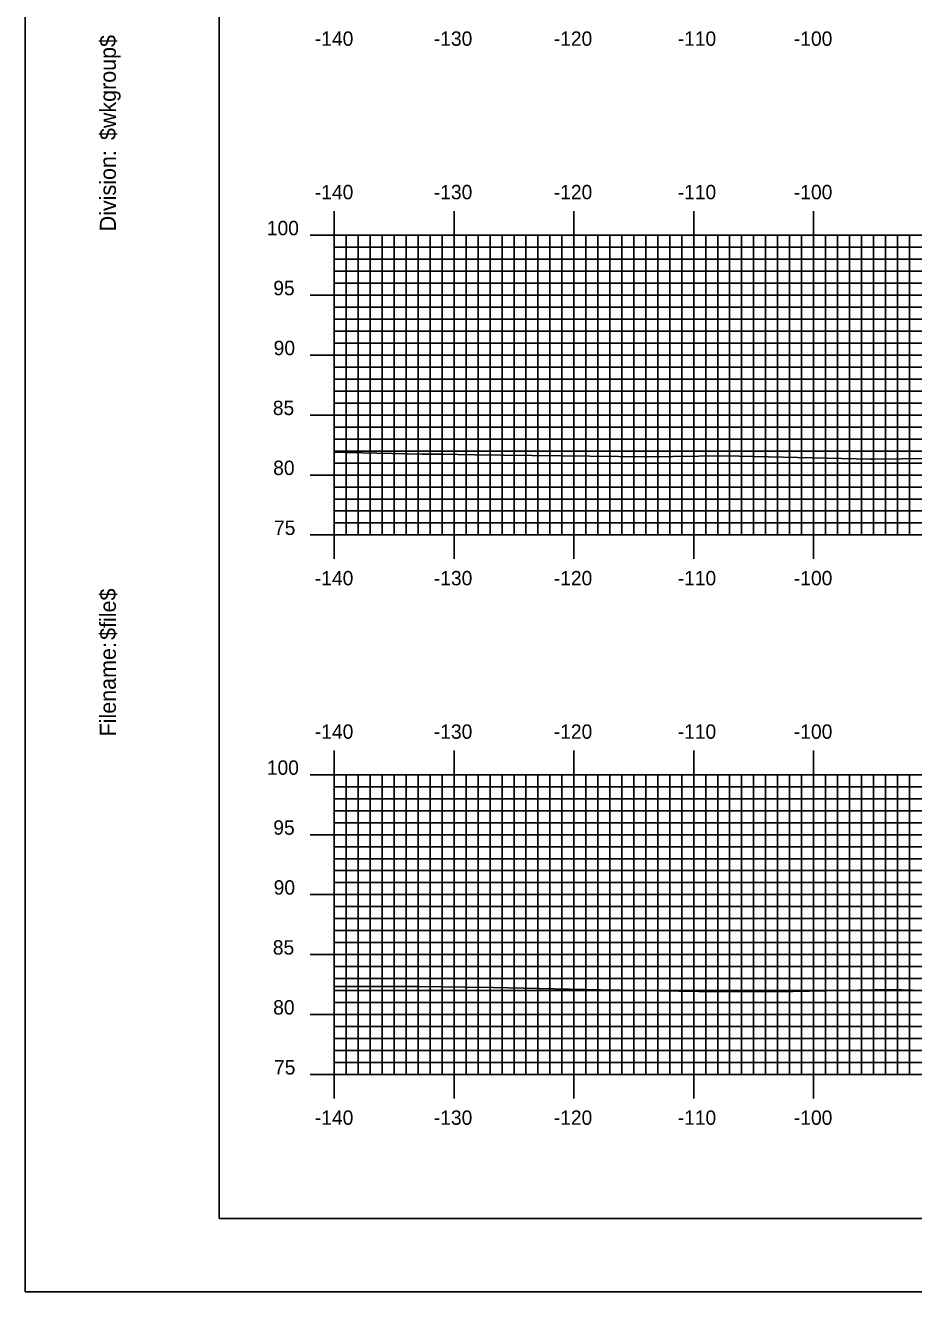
# Model space of a CAD drawing. Extents: x 856323 to 856666, y 364765 to 364985.
# Drawn here: x 856323 to 856397.1, y 364765.2 to 364870.8 of the extents above; entities that cross this region are included whole.
import ezdxf

# ---------------------------------------------------------------- set-up
doc = ezdxf.new("R2010")
doc.units = 0
for name, color, linetype in [('BORDER', 7, 'Continuous'), ('H_V ANNOTATION', 7, 'Continuous'), ('MAJOR', 7, 'Continuous'), ('MINOR', 7, 'Continuous'), ('PLOT BOUNDARY', 7, 'Continuous'), ('S_Roadway_Centerline', 7, 'Continuous')]:
    doc.layers.add(name, color=color, linetype=linetype)

msp = doc.modelspace()

# ---------------------------------------------------------------- linework, layer by layer
at = {"layer": 'BORDER'}
msp.add_lwpolyline([(856339.17, 364771.3), (856659.17, 364771.3), (856659.17, 364981.3), (856339.17, 364981.3)], close=True, dxfattribs=at)
at = {"layer": 'MAJOR'}
for p, q in [((856348.77, 364855.31), (856348.77, 364853.3)), ((856358.77, 364855.31), (856358.77, 364853.3)), ((856368.77, 364855.31), (856368.77, 364853.3)), ((856378.77, 364855.31), (856378.77, 364853.3)), ((856388.77, 364855.31), (856388.77, 364853.3)), ((856346.76, 364853.3), (856348.77, 364853.3)), ((856348.77, 364853.3), (856628.77, 364853.3)), ((856348.77, 364828.3), (856348.77, 364853.3)), ((856348.77, 364828.3), (856348.77, 364853.3)), ((856348.77, 364853.3), (856628.77, 364853.3)), ((856358.77, 364828.3), (856358.77, 364853.3)), ((856368.77, 364828.3), (856368.77, 364853.3)), ((856378.77, 364828.3), (856378.77, 364853.3)), ((856388.77, 364828.3), (856388.77, 364853.3)), ((856346.76, 364848.3), (856348.77, 364848.3)), ((856348.77, 364848.3), (856628.77, 364848.3)), ((856346.76, 364843.3), (856348.77, 364843.3)), ((856348.77, 364843.3), (856628.77, 364843.3)), ((856346.76, 364838.3), (856348.77, 364838.3)), ((856348.77, 364838.3), (856628.77, 364838.3)), ((856346.76, 364833.3), (856348.77, 364833.3)), ((856348.77, 364833.3), (856628.77, 364833.3)), ((856346.76, 364828.3), (856348.77, 364828.3)), ((856348.77, 364828.3), (856628.77, 364828.3)), ((856348.77, 364828.3), (856628.77, 364828.3)), ((856348.77, 364826.3), (856348.77, 364828.3)), ((856358.77, 364826.3), (856358.77, 364828.3)), ((856368.77, 364826.3), (856368.77, 364828.3)), ((856378.77, 364826.3), (856378.77, 364828.3)), ((856388.77, 364826.3), (856388.77, 364828.3)), ((856348.77, 364810.31), (856348.77, 364808.3)), ((856358.77, 364810.31), (856358.77, 364808.3)), ((856368.77, 364810.31), (856368.77, 364808.3)), ((856378.77, 364810.31), (856378.77, 364808.3)), ((856388.77, 364810.31), (856388.77, 364808.3)), ((856346.76, 364808.3), (856348.77, 364808.3)), ((856348.77, 364808.3), (856628.77, 364808.3)), ((856348.77, 364783.3), (856348.77, 364808.3)), ((856348.77, 364783.3), (856348.77, 364808.3)), ((856348.77, 364808.3), (856628.77, 364808.3)), ((856358.77, 364783.3), (856358.77, 364808.3)), ((856368.77, 364783.3), (856368.77, 364808.3)), ((856378.77, 364783.3), (856378.77, 364808.3)), ((856388.77, 364783.3), (856388.77, 364808.3)), ((856346.76, 364803.3), (856348.77, 364803.3)), ((856348.77, 364803.3), (856628.77, 364803.3)), ((856346.76, 364798.3), (856348.77, 364798.3)), ((856348.77, 364798.3), (856628.77, 364798.3)), ((856346.76, 364793.3), (856348.77, 364793.3)), ((856348.77, 364793.3), (856628.77, 364793.3)), ((856346.76, 364788.3), (856348.77, 364788.3)), ((856348.77, 364788.3), (856628.77, 364788.3)), ((856346.76, 364783.3), (856348.77, 364783.3)), ((856348.77, 364783.3), (856628.77, 364783.3)), ((856348.77, 364783.3), (856628.77, 364783.3)), ((856348.77, 364781.3), (856348.77, 364783.3)), ((856358.77, 364781.3), (856358.77, 364783.3)), ((856368.77, 364781.3), (856368.77, 364783.3)), ((856378.77, 364781.3), (856378.77, 364783.3)), ((856388.77, 364781.3), (856388.77, 364783.3))]:
    msp.add_line(p, q, dxfattribs=at)
at = {"layer": 'MINOR'}
for p, q in [((856349.77, 364828.3), (856349.77, 364853.3)), ((856350.77, 364828.3), (856350.77, 364853.3)), ((856351.77, 364828.3), (856351.77, 364853.3)), ((856352.77, 364828.3), (856352.77, 364853.3)), ((856353.77, 364828.3), (856353.77, 364853.3)), ((856354.77, 364828.3), (856354.77, 364853.3)), ((856355.77, 364828.3), (856355.77, 364853.3)), ((856356.77, 364828.3), (856356.77, 364853.3)), ((856357.77, 364828.3), (856357.77, 364853.3)), ((856359.77, 364828.3), (856359.77, 364853.3)), ((856360.77, 364828.3), (856360.77, 364853.3)), ((856361.77, 364828.3), (856361.77, 364853.3)), ((856362.77, 364828.3), (856362.77, 364853.3)), ((856363.77, 364828.3), (856363.77, 364853.3)), ((856364.77, 364828.3), (856364.77, 364853.3)), ((856365.77, 364828.3), (856365.77, 364853.3)), ((856366.77, 364828.3), (856366.77, 364853.3)), ((856367.77, 364828.3), (856367.77, 364853.3)), ((856369.77, 364828.3), (856369.77, 364853.3)), ((856370.77, 364828.3), (856370.77, 364853.3)), ((856371.77, 364828.3), (856371.77, 364853.3)), ((856372.77, 364828.3), (856372.77, 364853.3)), ((856373.77, 364828.3), (856373.77, 364853.3)), ((856374.77, 364828.3), (856374.77, 364853.3)), ((856375.77, 364828.3), (856375.77, 364853.3)), ((856376.77, 364828.3), (856376.77, 364853.3)), ((856377.77, 364828.3), (856377.77, 364853.3)), ((856379.77, 364828.3), (856379.77, 364853.3)), ((856380.77, 364828.3), (856380.77, 364853.3)), ((856381.77, 364828.3), (856381.77, 364853.3)), ((856382.77, 364828.3), (856382.77, 364853.3)), ((856383.77, 364828.3), (856383.77, 364853.3)), ((856384.77, 364828.3), (856384.77, 364853.3)), ((856385.77, 364828.3), (856385.77, 364853.3)), ((856386.77, 364828.3), (856386.77, 364853.3)), ((856387.77, 364828.3), (856387.77, 364853.3)), ((856389.77, 364828.3), (856389.77, 364853.3)), ((856390.77, 364828.3), (856390.77, 364853.3)), ((856391.77, 364828.3), (856391.77, 364853.3)), ((856392.77, 364828.3), (856392.77, 364853.3)), ((856393.77, 364828.3), (856393.77, 364853.3)), ((856394.77, 364828.3), (856394.77, 364853.3)), ((856395.77, 364828.3), (856395.77, 364853.3)), ((856396.77, 364828.3), (856396.77, 364853.3)), ((856348.77, 364852.3), (856628.77, 364852.3)), ((856348.77, 364852.3), (856350.77, 364852.3)), ((856348.77, 364851.3), (856628.77, 364851.3)), ((856348.77, 364851.3), (856350.77, 364851.3)), ((856348.77, 364850.3), (856628.77, 364850.3)), ((856348.77, 364850.3), (856350.77, 364850.3)), ((856348.77, 364849.3), (856628.77, 364849.3)), ((856348.77, 364849.3), (856350.77, 364849.3)), ((856348.77, 364847.3), (856628.77, 364847.3)), ((856348.77, 364847.3), (856350.77, 364847.3)), ((856348.77, 364846.3), (856628.77, 364846.3)), ((856348.77, 364846.3), (856350.77, 364846.3)), ((856348.77, 364845.3), (856628.77, 364845.3)), ((856348.77, 364845.3), (856350.77, 364845.3)), ((856348.77, 364844.3), (856628.77, 364844.3)), ((856348.77, 364844.3), (856350.77, 364844.3)), ((856348.77, 364842.3), (856628.77, 364842.3)), ((856348.77, 364842.3), (856350.77, 364842.3)), ((856348.77, 364841.3), (856628.77, 364841.3)), ((856348.77, 364841.3), (856350.77, 364841.3)), ((856348.77, 364840.3), (856628.77, 364840.3)), ((856348.77, 364840.3), (856350.77, 364840.3)), ((856348.77, 364839.3), (856628.77, 364839.3)), ((856348.77, 364839.3), (856350.77, 364839.3)), ((856348.77, 364837.3), (856628.77, 364837.3)), ((856348.77, 364837.3), (856350.77, 364837.3)), ((856348.77, 364836.3), (856628.77, 364836.3)), ((856348.77, 364836.3), (856350.77, 364836.3)), ((856348.77, 364835.3), (856628.77, 364835.3)), ((856348.77, 364835.3), (856350.77, 364835.3)), ((856348.77, 364834.3), (856628.77, 364834.3)), ((856348.77, 364834.3), (856350.77, 364834.3)), ((856348.77, 364832.3), (856628.77, 364832.3)), ((856348.77, 364832.3), (856350.77, 364832.3)), ((856348.77, 364831.3), (856628.77, 364831.3)), ((856348.77, 364831.3), (856350.77, 364831.3)), ((856348.77, 364830.3), (856628.77, 364830.3)), ((856348.77, 364830.3), (856350.77, 364830.3)), ((856348.77, 364829.3), (856628.77, 364829.3)), ((856348.77, 364829.3), (856350.77, 364829.3)), ((856349.77, 364783.3), (856349.77, 364808.3)), ((856350.77, 364783.3), (856350.77, 364808.3)), ((856351.77, 364783.3), (856351.77, 364808.3)), ((856352.77, 364783.3), (856352.77, 364808.3)), ((856353.77, 364783.3), (856353.77, 364808.3)), ((856354.77, 364783.3), (856354.77, 364808.3)), ((856355.77, 364783.3), (856355.77, 364808.3)), ((856356.77, 364783.3), (856356.77, 364808.3)), ((856357.77, 364783.3), (856357.77, 364808.3)), ((856359.77, 364783.3), (856359.77, 364808.3)), ((856360.77, 364783.3), (856360.77, 364808.3)), ((856361.77, 364783.3), (856361.77, 364808.3)), ((856362.77, 364783.3), (856362.77, 364808.3)), ((856363.77, 364783.3), (856363.77, 364808.3)), ((856364.77, 364783.3), (856364.77, 364808.3)), ((856365.77, 364783.3), (856365.77, 364808.3)), ((856366.77, 364783.3), (856366.77, 364808.3)), ((856367.77, 364783.3), (856367.77, 364808.3)), ((856369.77, 364783.3), (856369.77, 364808.3)), ((856370.77, 364783.3), (856370.77, 364808.3)), ((856371.77, 364783.3), (856371.77, 364808.3)), ((856372.77, 364783.3), (856372.77, 364808.3)), ((856373.77, 364783.3), (856373.77, 364808.3)), ((856374.77, 364783.3), (856374.77, 364808.3)), ((856375.77, 364783.3), (856375.77, 364808.3)), ((856376.77, 364783.3), (856376.77, 364808.3)), ((856377.77, 364783.3), (856377.77, 364808.3)), ((856379.77, 364783.3), (856379.77, 364808.3)), ((856380.77, 364783.3), (856380.77, 364808.3)), ((856381.77, 364783.3), (856381.77, 364808.3)), ((856382.77, 364783.3), (856382.77, 364808.3)), ((856383.77, 364783.3), (856383.77, 364808.3)), ((856384.77, 364783.3), (856384.77, 364808.3)), ((856385.77, 364783.3), (856385.77, 364808.3)), ((856386.77, 364783.3), (856386.77, 364808.3)), ((856387.77, 364783.3), (856387.77, 364808.3)), ((856389.77, 364783.3), (856389.77, 364808.3)), ((856390.77, 364783.3), (856390.77, 364808.3)), ((856391.77, 364783.3), (856391.77, 364808.3)), ((856392.77, 364783.3), (856392.77, 364808.3)), ((856393.77, 364783.3), (856393.77, 364808.3)), ((856394.77, 364783.3), (856394.77, 364808.3)), ((856395.77, 364783.3), (856395.77, 364808.3)), ((856396.77, 364783.3), (856396.77, 364808.3)), ((856348.77, 364807.3), (856628.77, 364807.3)), ((856348.77, 364807.3), (856350.77, 364807.3)), ((856348.77, 364806.3), (856628.77, 364806.3)), ((856348.77, 364806.3), (856350.77, 364806.3)), ((856348.77, 364805.3), (856628.77, 364805.3)), ((856348.77, 364805.3), (856350.77, 364805.3)), ((856348.77, 364804.3), (856628.77, 364804.3)), ((856348.77, 364804.3), (856350.77, 364804.3)), ((856348.77, 364802.3), (856628.77, 364802.3)), ((856348.77, 364802.3), (856350.77, 364802.3)), ((856348.77, 364801.3), (856628.77, 364801.3)), ((856348.77, 364801.3), (856350.77, 364801.3)), ((856348.77, 364800.3), (856628.77, 364800.3)), ((856348.77, 364800.3), (856350.77, 364800.3)), ((856348.77, 364799.3), (856628.77, 364799.3)), ((856348.77, 364799.3), (856350.77, 364799.3)), ((856348.77, 364797.3), (856628.77, 364797.3)), ((856348.77, 364797.3), (856350.77, 364797.3)), ((856348.77, 364796.3), (856628.77, 364796.3)), ((856348.77, 364796.3), (856350.77, 364796.3)), ((856348.77, 364795.3), (856628.77, 364795.3)), ((856348.77, 364795.3), (856350.77, 364795.3)), ((856348.77, 364794.3), (856628.77, 364794.3)), ((856348.77, 364794.3), (856350.77, 364794.3)), ((856348.77, 364792.3), (856628.77, 364792.3)), ((856348.77, 364792.3), (856350.77, 364792.3)), ((856348.77, 364791.3), (856628.77, 364791.3)), ((856348.77, 364791.3), (856350.77, 364791.3)), ((856348.77, 364790.3), (856628.77, 364790.3)), ((856348.77, 364790.3), (856350.77, 364790.3)), ((856348.77, 364789.3), (856628.77, 364789.3)), ((856348.77, 364789.3), (856350.77, 364789.3)), ((856348.77, 364787.3), (856628.77, 364787.3)), ((856348.77, 364787.3), (856350.77, 364787.3)), ((856348.77, 364786.3), (856628.77, 364786.3)), ((856348.77, 364786.3), (856350.77, 364786.3)), ((856348.77, 364785.3), (856628.77, 364785.3)), ((856348.77, 364785.3), (856350.77, 364785.3)), ((856348.77, 364784.3), (856628.77, 364784.3)), ((856348.77, 364784.3), (856350.77, 364784.3))]:
    msp.add_line(p, q, dxfattribs=at)
at = {"layer": 'PLOT BOUNDARY'}
msp.add_lwpolyline([(856322.98, 364765.18), (856662.98, 364765.18), (856662.98, 364985.18), (856322.98, 364985.18)], close=True, dxfattribs=at)
at = {"layer": 'S_Roadway_Centerline'}
for points in [[(856348.77, 364835.2), (856349.82, 364835.18), (856356.1, 364835.04), (856357.68, 364835.05), (856360.49, 364834.98), (856374.89, 364834.82), (856381.34, 364834.91), (856393.54, 364834.63), (856393.73, 364834.63), (856393.83, 364834.63), (856405.49, 364834.77), (856412.6, 364834.72), (856417.64, 364834.68), (856426.89, 364834.83), (856429.49, 364834.84), (856430.99, 364834.85), (856442.18, 364834.56), (856450.47, 364834.52), (856453.9, 364834.6), (856468.17, 364834.44), (856477.63, 364834.39)], [(856348.77, 364790.65), (856355.76, 364790.63), (856359.66, 364790.58), (856362.04, 364790.55), (856371, 364790.35), (856380.8, 364790.18), (856387.05, 364790.22), (856395.28, 364790.4), (856400.54, 364790.23), (856418.69, 364790.56), (856419.47, 364790.58), (856419.95, 364790.59), (856421.91, 364790.57), (856439.36, 364790.26), (856443.27, 364790.21), (856450.21, 364790.1), (856467.25, 364789.88), (856481.4, 364789.74)]]:
    msp.add_lwpolyline(points, dxfattribs=at)

# ---------------------------------------------------------------- texts
at = {"layer": 'BORDER'}
for s, p in [('$wkgroup$', (856330.54, 364861.24)), ('Division:', (856330.54, 364853.63)), ('$file$', (856330.54, 364819.55)), ('Filename:', (856330.54, 364811.5))]:
    msp.add_text(s, height=1.339, rotation=90, dxfattribs=at).set_placement(p)
at = {"layer": 'H_V ANNOTATION'}
for s, p in [('-140', (856347.15, 364869.1)), ('-130', (856357.08, 364869.1)), ('-120', (856367.09, 364869.1)), ('-110', (856377.43, 364869.1)), ('-100', (856387.13, 364869.1)), ('-140', (856347.15, 364856.3)), ('-130', (856357.08, 364856.3)), ('-120', (856367.09, 364856.3)), ('-110', (856377.43, 364856.3)), ('-100', (856387.13, 364856.3)), ('100', (856343.14, 364853.3)), ('95', (856343.68, 364848.3)), ('90', (856343.71, 364843.3)), ('85', (856343.64, 364838.3)), ('80', (856343.67, 364833.3)), ('75', (856343.74, 364828.3)), ('-140', (856347.15, 364824.1)), ('-130', (856357.08, 364824.1)), ('-120', (856367.09, 364824.1)), ('-110', (856377.43, 364824.1)), ('-100', (856387.13, 364824.1)), ('-140', (856347.15, 364811.3)), ('-130', (856357.08, 364811.3)), ('-120', (856367.09, 364811.3)), ('-110', (856377.43, 364811.3)), ('-100', (856387.13, 364811.3)), ('100', (856343.14, 364808.3)), ('95', (856343.68, 364803.3)), ('90', (856343.71, 364798.3)), ('85', (856343.64, 364793.3)), ('80', (856343.67, 364788.3)), ('75', (856343.74, 364783.3)), ('-140', (856347.15, 364779.1)), ('-130', (856357.08, 364779.1)), ('-120', (856367.09, 364779.1)), ('-110', (856377.43, 364779.1)), ('-100', (856387.13, 364779.1))]:
    msp.add_text(s, height=1.2, dxfattribs=at).set_placement(p)
at = {"layer": 'MAJOR'}
for p in [(856348.76, 364828.3), (856348.76, 364783.3)]:
    msp.add_text('-', height=0.012, dxfattribs=at).set_placement(p)

doc.saveas('drawing.dxf')
